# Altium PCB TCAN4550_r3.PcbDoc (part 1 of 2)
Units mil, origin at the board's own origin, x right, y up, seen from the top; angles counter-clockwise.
Board outline 2000 x 1400 mil, 2 copper layers (Top Layer, Bottom Layer), stack 62 mil thick; 75 components, 46 nets, 194 pads, 17 vias.
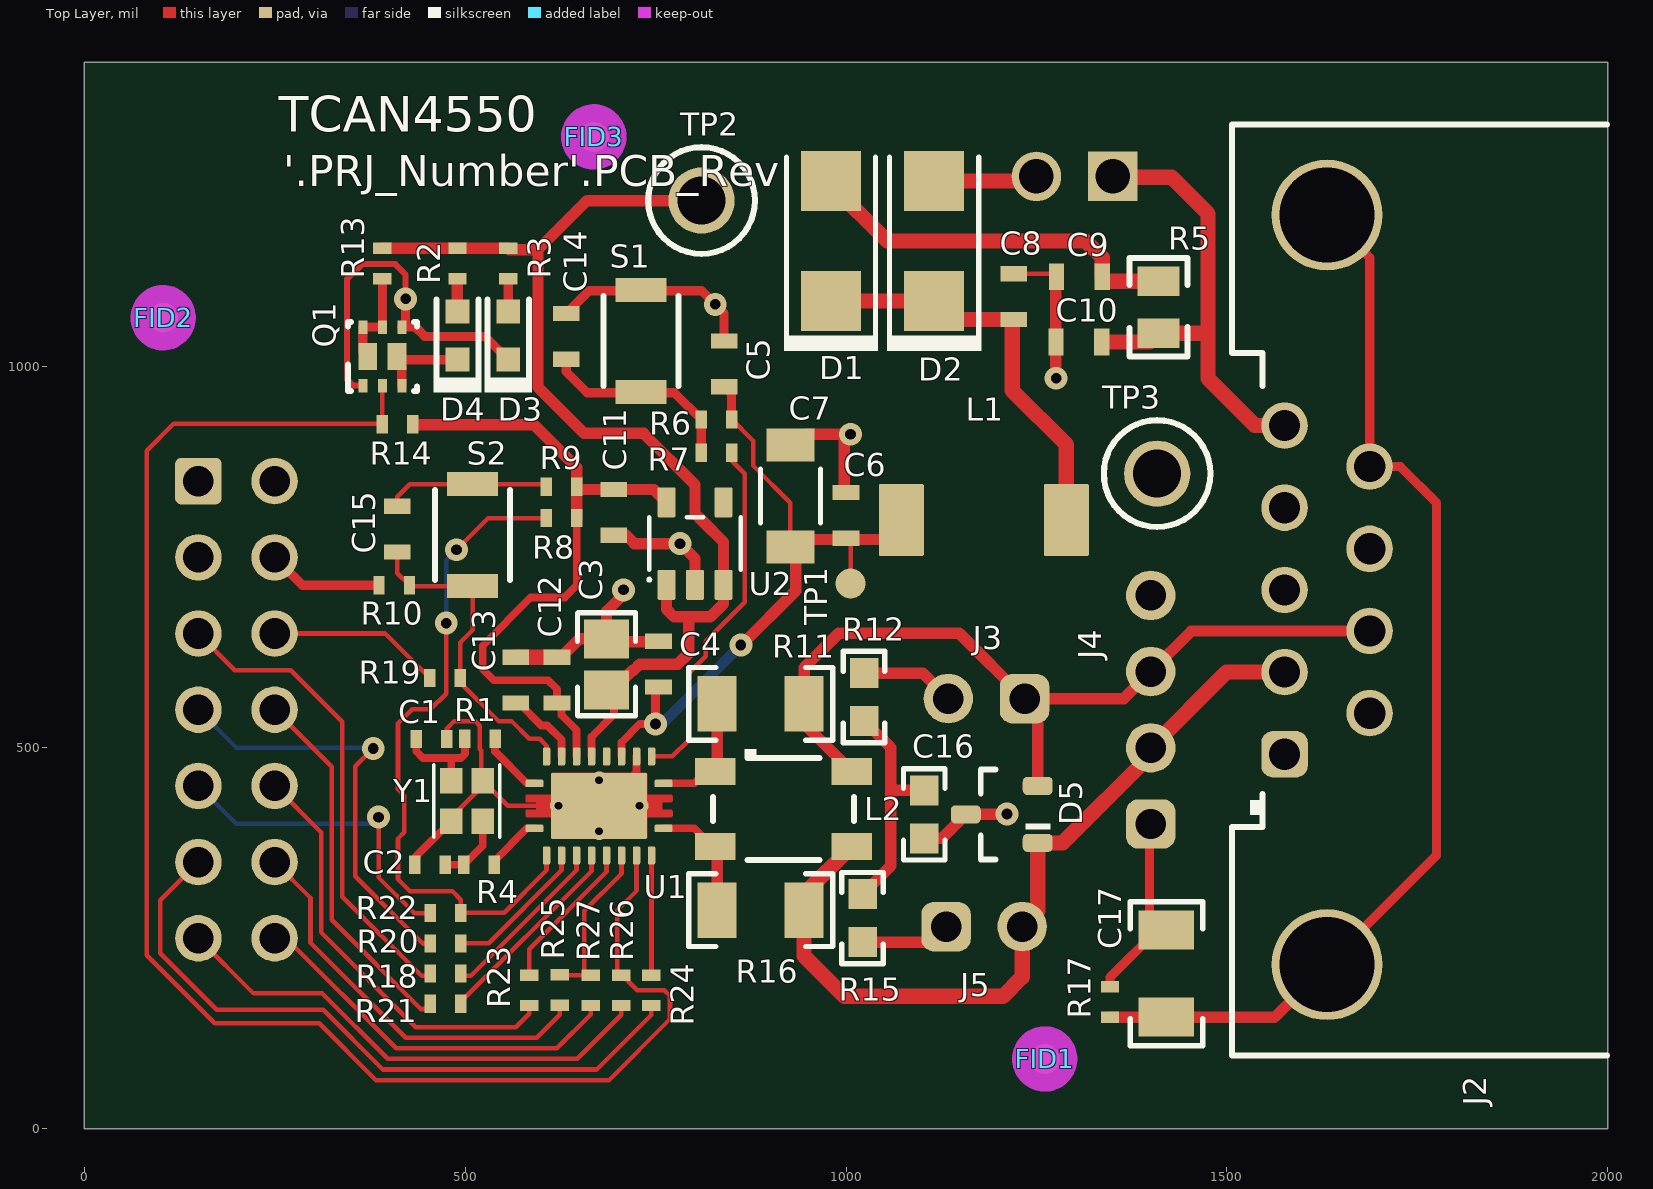
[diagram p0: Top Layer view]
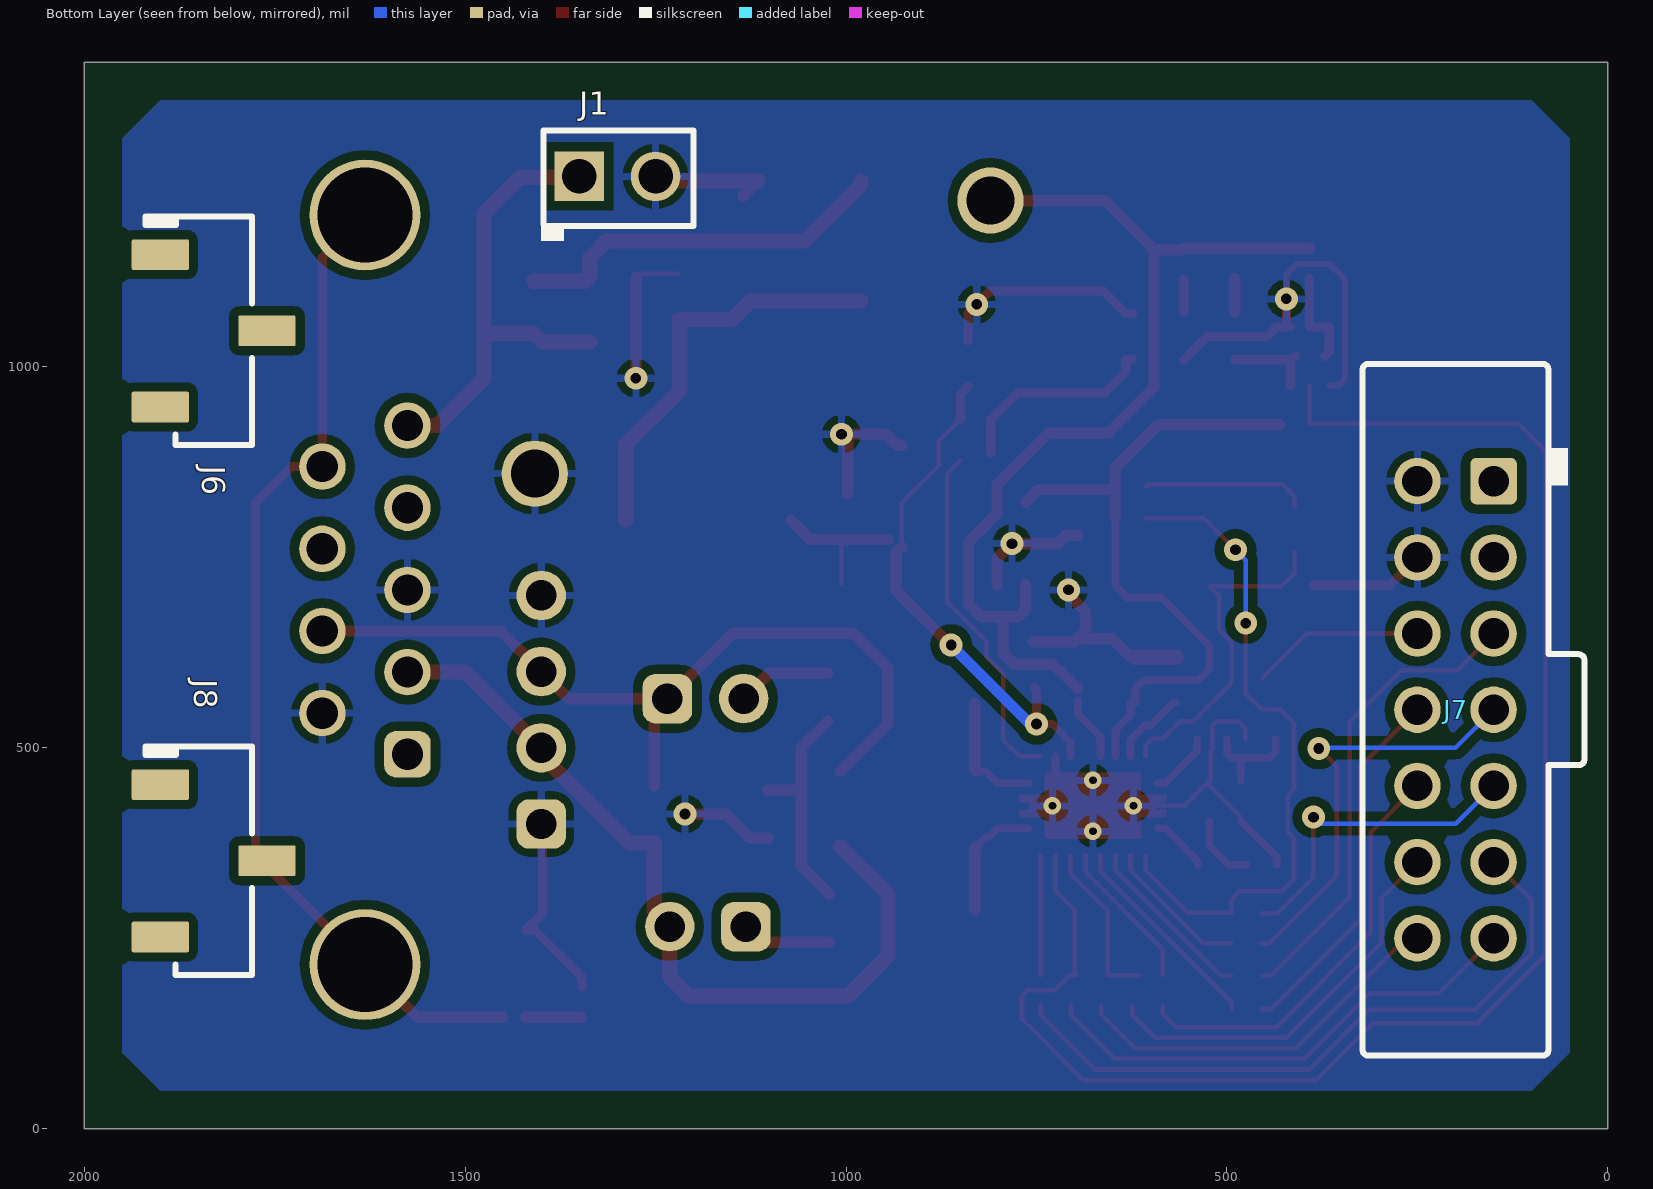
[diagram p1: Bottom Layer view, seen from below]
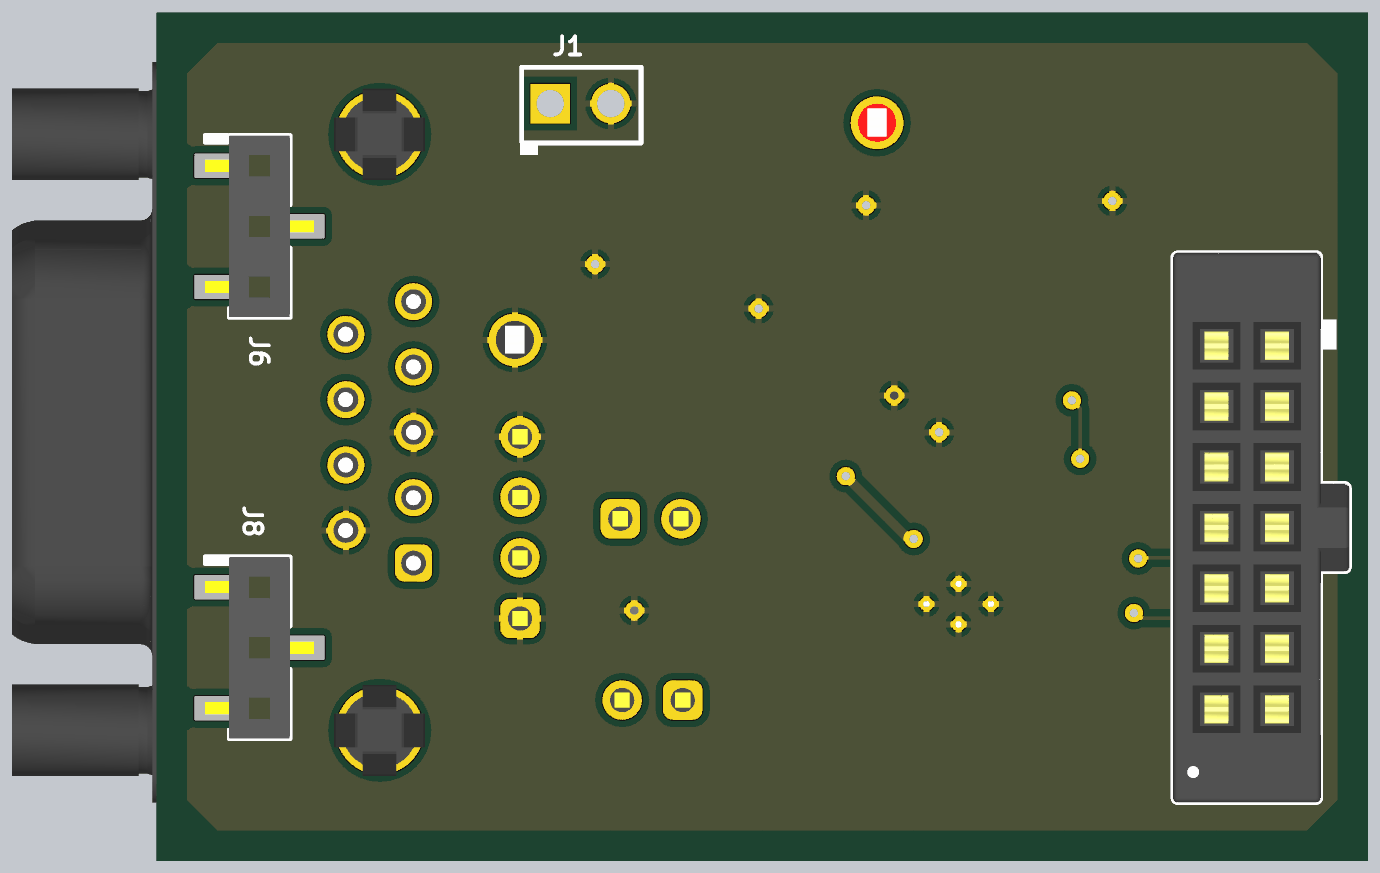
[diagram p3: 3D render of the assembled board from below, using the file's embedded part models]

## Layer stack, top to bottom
Top Solder: solder mask 0.4, Solder Resist, Dk 3.5
Top Layer: signal copper 1.4
Dielectric1: core 59.2, FR-4, Dk 4.8
Bottom Layer: signal copper 1.4
Bottom Solder: solder mask 0.4, Solder Resist, Dk 3.5

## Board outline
0,0 0,1400 2000,1400 2000,0

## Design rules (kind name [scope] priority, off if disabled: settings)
AcuteAngle [All] p1: minimum=4.50000000000000E+0001 checktracksonly=FALSE
AssemblyTestPointUsage [All] p1: valid=2
BoardOutlineClearance BoardOutlineClearance_MountingHoles [OnCopper and InComponentClass('Mounting Holes')] p1: gap=39.37 ignorepadtopadclearanceinfootprint=FALSE
BoardOutlineClearance BoardOutlineClearance_Poly [OnCopper and IsPoly] p2: gap=25 ignorepadtopadclearanceinfootprint=FALSE
BoardOutlineClearance [OnCopper and Not InComponentClass('Logo') and not InComponentClass('FiducialMark') and not InRegion(1000,500,4000,800) and not InPoly] p3: gap=60 ignorepadtopadclearanceinfootprint=FALSE
Clearance Clearance_Keepouts [((IsTrack Or IsArc) And Not InPoly) And IsFree and IsKeepOut vs ((IsTrack Or IsArc) And Not InPoly) And IsFree and IsKeepOut] p1: gap=0 ignorepadtopadclearanceinfootprint=FALSE
Clearance Clearance_Poly [InPolygon] p2: gap=12 ignorepadtopadclearanceinfootprint=TRUE
Clearance Clearance_FiducialMark [IsKeepOut and InComponentClass('FiducialMark') vs IsPad and InComponentClass('FiducialMark')] p3: gap=0 ignorepadtopadclearanceinfootprint=FALSE
Clearance [All] p4: gap=7.87 ignorepadtopadclearanceinfootprint=TRUE
ComponentClearance ComponentClearance_MountingHoles_FiducialMarks [InComponentClass('Mounting Holes') vs InComponentClass('FiducialMark')] p1: gap=50 collisioncheckmode=3 verticalgap=10 showdistances=FALSE
ComponentClearance ComponentClearance_Shunt [InComponentClass('Header') vs InComponentClass('Shunt')] p2: gap=0 collisioncheckmode=3 verticalgap=0 showdistances=FALSE
ComponentClearance ComponentClearance_Logo [InComponentClass('Logo')] p3: gap=10 collisioncheckmode=3 verticalgap=10 showdistances=FALSE
ComponentClearance ComponentClearance_ScrewToNut [(HasFootprint('NY PMS 440 0025 PH')) vs (HasFootprint('Keystone_1902C'))] p4: gap=5 collisioncheckmode=3 verticalgap=10 showdistances=FALSE
ComponentClearance ComponentClearance_MountingHoles [InComponentClass('Mounting Holes')] p5: gap=250 collisioncheckmode=3 verticalgap=100000 showdistances=FALSE
ComponentClearance ComponentClearance_SmallPassives [HasFootprint('0201*') or HasFootprint('0402*') or HasFootprint('0508') or HasFootprint('0603*') or HasFootprint('0612') or HasFootprint('0805*') or HasFootprint('0815*') or HasFootprint('0830*') or HasFootprint('1206*') or HasFootprint('1210*') or HasFootprint('1808*') or HasFootprint('1812*') or HasFootprint('1825*') or HasFootprint('2010*') or HasFootprint('2220*') or HasFootprint('2225*') or HasFootprint('2512*') or HasFootprint('2728*') or HasFootprint('3518*') vs HasFootprint('0201*') or HasFootprint('0402*') or HasFootprint('0508') or HasFootprint('0603*') or HasFootprint('0612') or HasFootprint('0805*') or HasFootprint('0815*') or HasFootprint('0830*') or HasFootprint('1206*') or HasFootprint('1210*') or HasFootprint('1808*') or HasFootprint('1812*') or HasFootprint('1825*') or HasFootprint('2010*') or HasFootprint('2220*') or HasFootprint('2225*') or HasFootprint('2512*') or HasFootprint('2728*') or HasFootprint('3518*')] p6: gap=14.96 collisioncheckmode=3 verticalgap=10 showdistances=FALSE
ComponentClearance ComponentClearance_THtoSMT [IsThruComponent vs IsSMTComponent] p7: gap=40 collisioncheckmode=3 verticalgap=30 showdistances=FALSE
ComponentClearance ComponentClearance_THtoTH [IsThruComponent vs IsThruComponent] p8: gap=30 collisioncheckmode=3 verticalgap=30 showdistances=FALSE
ComponentClearance [All] p9: gap=30 collisioncheckmode=3 verticalgap=10 showdistances=FALSE
DiffPairsRouting [All] p1: maxlimit=100 minlimit=10 mostfreqgap=10 toplayer_minwidth=15 toplayer_maxwidth=15 toplayer_prefwidth=15 bottomlayer_minwidth=15 bottomlayer_maxwidth=15 bottomlayer_prefwidth=15 maxuncoupledlength=1000
FabricationTestPointUsage TestPointUsage [All] p1: valid=2 allowmultiple=FALSE
FabricationTestpoint Testpoint [All] p1: side=3 testpointundercomponent=TRUE minsize=40 maxsize=100 preferedsize=60 minholesize=0 maxholesize=40 preferedholesize=32 testpointgrid=1 allowsidetop=TRUE allowsidebottom=TRUE usegrid=TRUE gridtolerance=0.01
FanoutControl Fanout_LCC [IsLCC] p1: bgadir=Out bgaviamode=Centered fanoutstyle=Auto fanoutdirection=Alternating viagrid=1 // Fanout_LCC (Default Rule)
FanoutControl Fanout_BGA [IsBGA] p2: bgadir=Out bgaviamode=Centered fanoutstyle=Auto fanoutdirection=Alternating viagrid=1 // Fanout_BGA (Default Rule)
FanoutControl Fanout_Default [All] p4: bgadir=Out bgaviamode=Centered fanoutstyle=Auto fanoutdirection=Alternating viagrid=1 // Fanout_Default (Default Rule)
FanoutControl Fanout_Small [(CompPinCount < 5)] p5: bgadir=Out bgaviamode=Centered fanoutstyle=Auto fanoutdirection=OutThenIn viagrid=1 // Fanout_Small (Default Rule)
HoleSize [All] p1: absolutevalues=TRUE maxlimit=251 minlimit=7.87 maxpercent=80.000 minpercent=20.000
MinimumAnnularRing MinimumAnnularRing_ThermalPadVias [IsVia and InAnyComponent] p1: minimumring=5.91
MinimumAnnularRing [All] p2: minimumring=7.87
MinimumSolderMaskSliver MinimumSolderMaskSliver_Logo [InComponentClass('Logo') vs InComponentClass('Logo')] p1: minsoldermaskwidth=0.7
MinimumSolderMaskSliver [All] p2: minsoldermaskwidth=3.94
PlaneConnect [All] p1: planeconnectstyle=Relief reliefexpansion=10 reliefentries=4 reliefconductorwidth=10 reliefairgap=10
PolygonConnect [All] p1: connectstyle=Relief reliefconductorwidth=10 reliefentries=4 polygonreliefangle="90 Angle" airgapwidth=10
RoutingVias ThermalPadVias [IsVia and InAnyComponent] p1: holewidth=7.87 width=19.68 viastyle="Through Hole" minholewidth=7.87 minwidth=19.68 maxholewidth=12.99 maxwidth=23.62
RoutingVias [All] p2: holewidth=16 width=34 viastyle="Through Hole" minholewidth=7.87 minwidth=26 maxholewidth=40 maxwidth=65
SilkToBoardRegionClearance [Not ((IsComment or IsDesignator) And (Hide <> 'False')) and not InRegion(1000,500,4000,800)] p1:
SilkToSilkClearance SilkToSilkClearance_Pb-FreeLogo [(HasFootprint('Pb-Free_Overlay_Medium') OR HasFootprint('Pb-Free_Overlay_Small')) vs (HasFootprint('Pb-Free_Overlay_Medium') OR HasFootprint('Pb-Free_Overlay_Small'))] p1: silktosilkclearance=0
SilkToSilkClearance [All] p2: silktosilkclearance=3.94
SilkToSolderMaskClearance SilkToComponentPadClearance [(IsPad or IsFill or IsRegion) and InAnycomponent] p1: minsilkscreentomaskgap=5 clearancetoexposedcopper=TRUE
SilkToSolderMaskClearance "Silk to Solder Mask Opening" [All] p2: minsilkscreentomaskgap=3.94 clearancetoexposedcopper=FALSE
SolderMaskExpansion [All] p1: expansion=1.97
UnRoutedNet [All] p1: checkbadconnections=TRUE
Width [All] p1: maxlimit=100 minlimit=6 preferedwidth=10 checkconnectedcopper=TRUE
14 further rules are at their usual default settings.

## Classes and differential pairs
component class Header: J3 J4 J5
component class FiducialMark: FID1 FID2 FID3
component class AssemblyNote: ZZ1 ZZ2 ZZ3 ZZ4

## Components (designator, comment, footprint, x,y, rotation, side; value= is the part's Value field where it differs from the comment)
C1 "CC0402DRNPO9BN8R0" 0402S 455.89,511.49 r0 top value=8pF
C2 "CC0402DRNPO9BN8R0" 0402S 454.24,346.43 r180 top value=8pF
C3 "CL21B106KOQNNNE" 0805 685.69,609.54 r90 top value=10uF
C4 "CGA3E2X7R1H104K080AA" 0603S 753.8,609.75 r90 top value=0.1uF
C5 "CGA3E2X7R1H104K080AA" 0603S 840,1004 r90 top value=0.1uF
C6 "UMK107AB7105KA-T" 0603S 1000,805 r90 top value=1uF
C7 "CL31B106KBHNNNE" 1206_180 927,830.43 r90 top value=10uF
C8 "CGA3E2X7R2A102K080AA" 0603S 1220,1092.16 r90 top value=1000pF
C9 "CGA3E2X7R2A102K080AA" 0603S 1306.31,1118.1 r180 top value=1000pF
C10 "CGA3E2X7R2A102K080AA" 0603S 1305.54,1032.57 r180 top value=1000pF
C11 "CGA3E2X7R1H104K080AA" 0603S 695.33,809 r270 top value=0.1uF
C12 "CGA3E2X7R1H104K080AA" 0603S 620.73,588.9 r90 top value=0.1uF
C13 "C0603C334K4RACTU" 0603S 566.37,588.9 r90 top value=0.33uF
C14 "06035A101JAT2A" 0603S 632.78,1040 r90 top value=100pF
C15 "06035A101JAT2A" 0603S 411.13,787.12 r90 top value=100pF
C16 "06031C472KAT2A" 0603 1102.8,412.74 r90 top value=4700pF
C17 "12061C103JAT2A" 1206 1420.58,203.51 r90 top value=0.01uF
D1 "MBRA140T3G" SMA 980.32,1165.07 r90 top value=40V
D2 "3SMAJ5936B-TP" SMA 1115.6,1165.07 r90 top value=30V
D3 "150060GS75000" WL-SMCW_GREEN 556.7,1040.86 r90 top value=Green
D4 "150060BS75000" WL-SMCW_Blue 490.1,1040.86 r90 top value=Blue
D5 "PESD1CAN,215" SOT-23 1204.42,412.6 r180 top value=24V
FID1 "Fiducial" Fiducial10-20 1260.92,91.64 r0 top
FID2 "Fiducial" Fiducial10-20 103.75,1064.48 r0 top
FID3 "Fiducial" Fiducial10-20 669,1301.88 r0 top
J1 "SSW-101-23-F-D" Samtec_SSW-101-23-x-D 1300,1250 r90 bottom
J2 "5747840-5" TE_5747840-5 2006.81,707.26 r90 top
J3 "TSW-102-07-G-S" TSW-102-07-G-S 1184.31,564.55 r180 top
J4 "TSW-104-07-G-S" TSW-104-07-G-S 1400,550 r90 top
J5 "TSW-102-07-G-S" TSW-102-07-G-S 1181.27,265.3 r0 top
J6 "SSM-103-S-SV" Samtec_SSM-103-x-SV 1829.98,1047.31 r270 bottom
J7 "SFH11-PBPC-D07-ST-BK" Sullins_SFH11-xxxC-D07-ST-BK 200,550 r270 bottom
J8 "SSM-103-S-SV" Samtec_SSM-103-x-SV 1829.98,351.72 r270 bottom
L1 "B82462A4472M000" B82462A4 1180.91,799 r0 top value=4.7uH
L2 "ACT45B-101-2P-TL003" ACT45B 917.96,419.83 r0 top value=100uH
Q1 "CSD85301Q2" DQK0006B 391.4,1013.87 r90 top value=20V
R1 "RC0402JR-070RL" 0402S 519.38,511.86 r180 top value=0
R2 "RC0402FR-071KL" 0402S 490,1135.47 r90 top value=1.00k
R3 "RC0402FR-0710KL" 0402S 556.7,1135.47 r90 top value=10.0k
R4 "RC0402JR-070RL" 0402S 518.14,346.43 r180 top value=0
R5 "5106" 5106 1410.15,1078.75 r270 top value=0
R6 "ERJ-2RKF3301X" 0402S 829.89,931 r0 top value=3.30k
R7 "CRCW040233K2FKED" 0402S 830,887.08 r0 top value=33.2k
R8 "RC0402FR-0710KL" 0402S 626.63,801.58 r0 top value=10.0k
R9 "RC0402FR-071KL" 0402S 626.63,842.48 r0 top value=1.00k
R10 "RC1005F104CS" 0402S 407.05,713.42 r0 top value=100k
R11 "ERJ-8GEY0R00V" 1206 887.96,557.75 r0 top value=0
R12 "RC0603FR-0760R4L" 0603 1023.79,566.61 r90 top value=60.4
R13 "RC0402FR-0710KL" 0402S 391.44,1135.47 r90 top value=10.0k
R14 "RC0402FR-0710KL" 0402S 411.13,924.5 r0 top value=10.0k
R15 "RC0603FR-0760R4L" 0603 1021.72,276.36 r90 top value=60.4
R16 "ERJ-8GEY0R00V" 1206 887.96,286.88 r0 top value=0
R17 "ERJ-2RKF1004X" 0402S 1346.5,166.15 r270 top value=1.00Meg
R18 "RC0402JR-070RL" 0402S 474.24,203.72 r180 top value=0
R19 "RC0402JR-070RL" 0402S 473.57,591.55 r0 top value=0
R20 "RC0402JR-070RL" 0402S 474.34,243.12 r180 top value=0
R21 "RC0402JR-070RL" 0402S 474.24,164.1 r0 top value=0
R22 "RC0402JR-070RL" 0402S 474.34,283.14 r180 top value=0
R23 "RC0402JR-070RL" 0402S 584.26,181.74 r90 top value=0
R24 "RC0402JR-070RL" 0402S 744.53,181.74 r270 top value=0
R25 "RC0402JR-070RL" 0402S 624.46,181.91 r90 top value=0
R26 "RC0402JR-070RL" 0402S 705,181.74 r270 top value=0
R27 "RC0402JR-070RL" 0402S 665,181.74 r90 top value=0
S1 "B3U-1000P" SW_B3U-1000P 730.74,1034 r270 top
S2 "B3U-1000P" SW_B3U-1000P 510,779 r270 top
TP1 "TP_SM_1MM" TP_SM_1MM 1006,715.63 r0 top
TP2 "5010" Keystone5010 810.46,1218.28 r180 top
TP3 "5011" Keystone5011 1408.36,859.88 r180 top
U1 "TCAN4550RGYRQ1" RGY0020C 675.85,423.77 r90 top
U2 "TPS73433TDDCRQ1" DDC0005A_N 801.82,768 r90 top
Y1 "NX2016SA-40M-STD-CZS-3" XTAL_NX2016SA 502.33,430.01 r270 top
ZZ1 "This Assembly Note is for PCB labels only" AssemblyNoteLabel 35,2288 r0 top
ZZ2 "These assemblies are ESD sensitive, ESD precautions shall be observed." AssemblyNote 35,2179.11 r0 top
ZZ3 "These assemblies must be clean and free from flux and all contaminants. Use of no clean flux is not acceptable." AssemblyNote 35,2090.56 r0 top
ZZ4 "These assemblies must comply with workmanship standards IPC-A-610 Class 2, unless otherwise specified." AssemblyNote 35,2002 r0 top

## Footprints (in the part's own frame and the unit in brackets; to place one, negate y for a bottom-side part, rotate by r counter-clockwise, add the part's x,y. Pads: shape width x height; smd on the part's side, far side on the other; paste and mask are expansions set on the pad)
0402S [mil] "Based on C0402S footprint from PADS legacy"
  rect 15x24 smd: 1(-20,0) 2(20,0)
  body extent -22,-12 22,12, height 24
0603 [mm] "0603 from SM-752 data"
  rect 1x0.95 smd: 1(-0.8,0) 2(0.8,0)
  silkscreen extent -1.52,-0.69 1.52,0.69, body extent -0.87,-0.47 0.87,0.47, height 1
0603S [mil]
  rect 20x35 smd: 1(-30,0) 2(30,0)
  body extent -34,-19 34,19, height 39
0805 [mm] "0805 from SM-752 data"
  rect 1.3x1.5 smd: 1(-0.85,0) 2(0.85,0)
  silkscreen extent -1.72,-0.97 1.72,0.97, body extent -1.1,-0.72 1.1,0.72, height 1.45
1206 [mm] "1206 from SM-752 data"
  rect 1.3x1.85 smd: 1(-1.45,0) 2(1.45,0)
  silkscreen extent -2.4,-1.21 2.4,1.21, body extent -1.7,-0.9 1.7,0.9, height 1.35
1206_180 [mm] "1206_180"
  rect 1.1x1.6 smd: 1(-1.7,0) 2(1.7,0)
  silkscreen extent -0.9,-1 0.9,1, body extent -1.75,-0.95 1.75,0.95, height 1.8
5106 [mm] "Keystone"
  rect 0.99x1.4 smd: 1(-0.85,0) 2(0.88,0)
  silkscreen extent -1.63,-0.97 1.65,0.97, body extent -1.06,-0.69 1.06,0.69, height 0.84
ACT45B [mm] "SMD, 4-Leads, Body 4.7 x 3.7 mm"
  rect 1.35x0.9 smd: 1(-2.275,1.25) 2(-2.275,-1.25) 3(2.275,-1.25) 4(2.275,1.25)
  silkscreen extent -2.35,-1.7 2.35,2, body extent -2.35,-1.7 2.35,1.7, height 3
AssemblyNote [mil] "Assembly Note"
AssemblyNoteLabel [mil] "Assembly Note for PCB Labels"
B82462A4 [mm] "SMD, 2-Leads, Body 6x6mm"
  rrect7% 1.5x2.4 smd: 1(-2.75,0) 2(2.75,0)
  body extent -3.1,-3.05 3.1,2.94, height 3
DDC0005A_N [mm]
  rrect17% 1x0.6 smd: 1(-1.375,0.95) 2(-1.375,0) 3(-1.375,-0.95) 4(1.375,-0.95) 5(1.375,0.95)
  silkscreen extent -1.25,-1.52 0.88,1.57, body extent -1.41,-1.45 1.41,1.45, height 1.1
DQK0006B [mm] "TI"
  rect 0.45x0.3 smd: 1(-0.975,0.65) 2(-0.975,0) 3(-0.975,-0.65) 4(0.975,-0.65) 5(0.975,0) 6(0.975,0.65)
  rect 0.9x0.625 smd paste-0.025: 7(0,0.488) 8(0,-0.488)
  silkscreen extent -1.15,-1.15 1.15,1.15, body extent -1.05,-1.05 1.05,1.05, height 0.8
Fiducial10-20 [mm]
  round 1 smd mask+0.5: 1(0,0)
  Top Layer keep-out circle w1.178: c0,0 r0.5
Keystone5010 [mil] "Keystone Multipurpose loops"
  round 87 hole 63: 1(0,0)
  silkscreen extent -70,-70 70,70, body extent -63,-63 63,62, height 319
Keystone5011 [mil] "Keystone Multipurpose loops"
  round 87 hole 63: 1(0,0)
  silkscreen extent -70,-70 70,70, body extent -63,-63 63,62, height 319
RGY0020C [mm] "VQFN-20"
  rrect40% 0.25x0.6 smd: 1(-0.75,2.15) 10(-0.75,-2.15) 11(0.75,-2.15) 20(0.75,2.15)
  rrect40% 0.6x0.25 smd: 2(-1.65,1.75) 3(-1.65,1.25) 4(-1.65,0.75) 5(-1.65,0.25) 6(-1.65,-0.25) 7(-1.65,-0.75) 8(-1.65,-1.25) 9(-1.65,-1.75) 12(1.65,-1.75) 13(1.65,-1.25) 14(1.65,-0.75) 15(1.65,-0.25) 16(1.65,0.25) 17(1.65,0.75) 18(1.65,1.25) 19(1.65,1.75)
  rrect5% 2.2x3.2 smd paste-1.4: 21(0,0)
  Top Layer region: -0.375,-1.6 -1.05,-1.6 -1.069,-1.596 -1.085,-1.585 -1.096,-1.569 -1.1,-1.55 -1.1,-1.55 -1.1,1.55 -1.096,1.569 -1.085,1.585 -1.069,1.596 -1.05,1.6 -1.05,1.6 -0.375,1.6 -0.375,2.4 -0.371,2.419 -0.36,2.435 -0.344,2.446 -0.325,2.45 -0.325,2.45 -0.175,2.45 -0.156,2.446 -0.14,2.435 -0.129,2.419 -0.125,2.4 -0.125,2.4 -0.125,2.1 0.125,2.1 0.125,2.4 0.129,2.419 0.14,2.435 0.156,2.446 0.175,2.45 0.175,2.45 0.325,2.45 0.344,2.446 0.36,2.435 0.371,2.419 0.375,2.4 0.375,2.4 0.375,1.6 1.05,1.6 1.069,1.596 1.085,1.585 1.096,1.569 1.1,1.55 1.1,1.55 1.1,-1.55 1.096,-1.569 1.085,-1.585 1.069,-1.596 1.05,-1.6 1.05,-1.6 0.375,-1.6 0.375,-2.4 0.371,-2.419 0.36,-2.435 0.344,-2.446 0.325,-2.45 0.325,-2.45 0.325,-2.45 0.175,-2.45 0.175,-2.45 0.156,-2.446 0.14,-2.435 0.129,-2.419 0.125,-2.4 0.125,-2.4 0.125,-2.1 -0.125,-2.1 -0.125,-2.4 -0.129,-2.419 -0.14,-2.435 -0.156,-2.446 -0.175,-2.45 -0.175,-2.45 -0.175,-2.45 -0.325,-2.45 -0.325,-2.45 -0.344,-2.446 -0.36,-2.435 -0.371,-2.419 -0.375,-2.4 -0.375,-2.4
  body extent -1.75,-2.25 1.75,2.25, height 1
Samtec_SSM-103-x-SV [mm] "Receptacle, 2.54mm, 3x1, SMT"
  rrect10% 1.02x1.905 smd: 1(-2.54,-1.777) 2(0,1.777) 3(2.54,-1.777)
  silkscreen extent -3.81,-2.27 3.81,1.28, body extent -3.81,-2.29 3.81,2.29, height 7.51
Samtec_SSW-101-23-x-D [mm] "SAMTEC"
  rect 1.65x1.65 hole 1.15: 1(0,1.27)
  round 1.65 hole 1.15: 2(0,-1.27)
  silkscreen extent -2.16,-2.54 1.52,2.54, body extent -1.52,-2.49 1.52,2.46, height 8.59
SMA [mm] "Molded Diode, 2-Leads, Body 4.3x2.6mm, IPC Medium Density, based on OnSemi component dimensions and land pattern"
  rect 2x2 smd: 1(-2,0) 2(2,0)
  silkscreen extent -3.66,-1.57 2.79,1.57, body extent -2.6,-1.3 2.6,1.3, height 2.42
SOT-23 [mm] "SOT23, 3-Leads, Body 2.9x1.3mm, Pitch 0.95mm, Lead Span 2.5mm, IPC Medium Density"
  rrect50% 1x0.6 smd: 1(-1.2,0.95) 2(-1.2,-0.95) 3(1.2,0)
  silkscreen extent -1.63,-1.5 0.7,1.5, body extent -1.16,-1.45 1.21,1.45, height 1
Sullins_SFH11-xxxC-D07-ST-BK [mm] "Receptacle, 2.54mm, 7x2, TH"
  rrect25% 1.55x1.55 hole 1.02: 1(-7.62,1.27)
  round 1.55 hole 1.02: 2(-7.62,-1.27) 3(-5.08,1.27) 4(-5.08,-1.27) 5(-2.54,1.27) 6(-2.54,-1.27) 7(0,1.27) 8(0,-1.27) 9(2.54,1.27) 10(2.54,-1.27) 11(5.08,1.27) 12(5.08,-1.27) 13(7.62,1.27) 14(7.62,-1.27)
  silkscreen extent -11.53,-3.1 11.53,4.3, body extent -11.53,-3.1 11.53,4.3, height 8.71
SW_B3U-1000P [mm] "OMRON"
  rect 0.8x1.7 smd: 1(-1.7,0) 2(1.7,0)
  silkscreen extent -1.5,-1.25 1.5,1.25, body extent -1.5,-1.25 1.5,1.25, height 1.75
TE_5747840-5 [mm] "D-Sub, 2.74mm, 9 Position, R/A, TH"
  rrect50% 1.55x1.55 hole 1.04: 1(-5.48,10.954)
  round 1.55 hole 1.04: 2(-2.74,10.954) 3(0,10.954) 4(2.74,10.954) 5(5.48,10.954) 6(-4.11,8.114) 7(-1.37,8.114) 8(1.37,8.114) 9(4.11,8.114)
  round 3.7 hole 3.17: 10(12.495,9.534) 11(-12.495,9.534)
  silkscreen extent -15.52,0.2 15.52,12.71, body extent -15.52,-5.89 15.52,12.71, height 12.55
TP_SM_1MM [mm] "1mm Test Point, SMT"
  round 1 smd paste-0.5: 1(0,0)
TSW-102-07-G-S [mm] "Samtec 100mil, 1x2, 230 mil above insulator"
  rrect50% 1.65x1.65 hole 1.016: 1(-1.27,0)
  round 1.65 hole 1.016: 2(1.27,0)
  body extent -2.54,-1.27 2.54,1.27, height 8.38
TSW-104-07-G-S [mm] "Samtec 100mil, 1x4, 230 mil above insulator"
  rrect50% 1.65x1.65 hole 1.016: 1(-3.81,0)
  round 1.65 hole 1.016: 2(-1.27,0) 3(1.27,0) 4(3.81,0)
  body extent -5.08,-1.27 5.08,1.27, height 8.38
WL-SMCW_Blue [mm] "SMD, 2-Leads, Body 1.6x0.8mm"
  rect 0.8x0.8 smd: 1(-0.8,0) 2(0.8,0)
  silkscreen extent -1.9,-0.8 1.2,0.8, body extent -0.85,-0.45 0.85,0.45, height 0.8
WL-SMCW_GREEN [mm] "WURTH"
  rect 0.8x0.8 smd: 1(-0.8,0) 2(0.8,0)
  silkscreen extent -1.9,-0.8 1.2,0.8, body extent -0.85,-0.45 0.85,0.45, height 0.8
XTAL_NX2016SA [mm] "2.0 x 1.6 x 0.45mm Crystal"
  rect 0.85x0.75 smd mask+0.076: 1(-0.675,-0.525) 2(0.675,-0.525) 3(0.675,0.525) 4(-0.675,0.525)
  silkscreen extent -1.2,-1.1 1.2,1.1, body extent -1,-0.8 1,0.8, height 0.51

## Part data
C1 C2: library part CMP-0860185-1, "CAP, CERM, 8 pF, 50 V,+/- 6.25%, C0G/NP0, 0402", Cap_Case=0402, Manufacturer=Yageo, TempCo=C0G/NP0, Tolerance_%=6.25%, Value2=50V, ValueDisplayed=8pF
C3: library part CMP-0007995-2, "CAP, CERM, 10 uF, 16 V, +/- 10%, X7R, 0805", Cap_Case=0805, Manufacturer="Samsung Electro-Mechanics", TempCo=X7R, Tolerance_%=10%, Value1=Unknown, Value2=16V, ValueDisplayed=10uF
C4 C5 C11 C12: library part CMP-0007078-4, "CAP, CERM, 0.1 uF, 50 V, +/- 10%, X7R, AEC-Q200 Grade 1, 0603", Cap_Case=0603, Manufacturer=TDK, Supplier Part Number 1=445-5666-1-ND, TempCo=X7R, Tolerance_%=10%, Value1="0.0296 ohm", Value2=50V, ValueDisplayed=0.1uF
C6: library part CMP-0007508-5, "CAP, CERM, 1 uF, 50 V, +/- 10%, X7R, 0603", Cap_Case=0603, Manufacturer="Taiyo Yuden", Supplier Part Number 1=587-3247-1-ND, TempCo=X7R, Tolerance_%=10%, Value1=Unknown, Value2=50V, ValueDisplayed=1uF
C7: library part CMP-0008802-2, "CAP, CERM, 10 uF, 50 V, +/- 10%, X7R, 1206", Cap_Case=1206, Manufacturer=Samsung, Supplier Part Number 1=1276-6767-1-ND, TempCo=X7R, Tolerance_%=10%, Value1=Unknown, Value2=50V, ValueDisplayed=10uF
C8 C9 C10: library part CMP-0007081-4, "CAP, CERM, 1000 pF, 100 V, +/- 10%, X7R, AEC-Q200 Grade 1, 0603", Cap_Case=0603, Manufacturer=TDK, Supplier Part Number 1=445-5806-1-ND, TempCo=X7R, Tolerance_%=10%, Value1="1.97137 ohm", Value2=100V, ValueDisplayed=1000pF
C13: library part CMP-0006924-4, "CAP, CERM, 0.33 uF, 16 V, +/- 10%, X7R, 0603", Cap_Case=0603, Manufacturer=Kemet, Supplier Part Number 1=399-4916-1-ND, TempCo=X7R, Tolerance_%=10%, Value1=Unknown, Value2=16V, ValueDisplayed=0.33uF
C14 C15: library part CMP-0006763-4, "CAP, CERM, 100 pF, 50 V, +/- 5%, C0G/NP0, 0603", Cap_Case=0603, Manufacturer=AVX, Supplier Part Number 1=478-1175-1-ND, TempCo=C0G/NP0, Tolerance_%=5%, Value1="0.119 ohm", Value2=50V, ValueDisplayed=100pF
C16: library part CMP-0006746-5, "CAP, CERM, 4700 pF, 100 V, +/- 10%, X7R, 0603", Cap_Case=0603, Manufacturer=AVX, Supplier Part Number 1=478-1203-1-ND, TempCo=X7R, Tolerance_%=10%, Value1="0.136 ohm", Value2=100V, ValueDisplayed=4700pF
C17: library part CMP-0008484-2, "CAP, CERM, 0.01 uF, 100 V, +/- 5%, X7R, 1206", Cap_Case=1206, Manufacturer=AVX, Supplier Part Number 1=478-3783-1-ND, TempCo=X7R, Tolerance_%=5%, Value1="0.119 ohm", Value2=100V, ValueDisplayed=0.01uF
D1: library part CMP-0028550-2, "Diode, Schottky, 40 V, 1 A, SMA", Manufacturer="ON Semiconductor", Value1=1A, Value2=0.55V
D2: library part CMP-0005515-4, "Diode, Zener, 30 V, 3 W, SMA", Manufacturer="Micro Commercial Components", Power_W=3W
D3: library part CMP-0002905-2, "LED, Green, SMD", Color=Green, Manufacturer="Wurth Elektronik", Value1=W, Value2=3.2V
D4: library part CMP-0002946-3, "LED, Blue, SMD", Color=Blue, Manufacturer="Wurth Elektronik", Power_TotalModule=105mW, Value1=0.105W, Value2=3.2V
D5: library part CMP-0005920-3, "Diode, TVS, Bi, 24 V, 70 Vc, AEC-Q101, SOT-23", Manufacturer="NXP Semiconductor", Value1=200W
FID1 FID2 FID3: library part CMP-0077181-1, "Fiducial mark.  There is nothing to buy or mount.", Manufacturer=N/A
J1: library part CMP-0055671-1, "Receptacle, 2.54mm, 1x2, Gold, TH", Color=Black, Current_A=5.7A, Manufacturer=Samtec, Voltage_V=550V
J2: library part CMP-0054938-4, "D-Sub, 2.74mm, 9 Position, R/A, TH", Color=Black, Manufacturer="TE Connectivity", Supplier Part Number 1=A32093-ND
J3 J5: library part CMP-0075405-2, "Header, 100mil, 2x1, Gold, TH", Color=Black, Current_A=6.3A, Manufacturer=Samtec, Supplier Part Number 1=SAM1029-02-ND, Voltage_V=550V
J4: library part CMP-0075409-2, "Header, 100mil, 4x1, Gold, TH", Color=Black, Current_A=6.3A, Manufacturer=Samtec, Supplier Part Number 1=SAM1029-04-ND, Voltage_V=550V
J6 J8: library part CMP-0078183-1, "Receptacle, 2.54mm, 3x1, Gold with Tin tail, SMT", Color=Black, Current_A=5.2A, Manufacturer=Samtec, Supplier Part Number 1=SAM1152-03-ND, Voltage_V=405V
J7: library part CMP-0054668-1, "Receptacle, 2.54mm, 7x2, Gold, Black, TH", Color=Black, Current_A=3A, Manufacturer="Sullins Connector Solutions", Supplier Part Number 1=S9195-ND, Voltage_V=1kV
L1: library part CMP-0001617-1, "Inductor, Wirewound, Ferrite, 4.7 µH, 1.65 A, 0.08 ohm, AEC-Q200 Grade 0, SMD", Manufacturer=TDK, Supplier Part Number 1=495-2665-1-ND, Value1="0.08 ohm", Value2=1.65A, ValueDisplayed=4.7µH
L2: library part CMP-0062430-2, "Inductor, Ferrite, 100 uH, 0.15 A, 2 ohm, SMD", Manufacturer=TDK, Supplier Part Number 1=445-3959-1-ND, Value1="2 ohm", Value2=0.15A, ValueDisplayed=100uH
Q1: library part CMP-0000208-1, "MOSFET, 2-CH, N-CH, 20 V, 6.7 A, DQK0006B (WSON-6)", Alternate Manufacturer=None, Manufacturer="Texas Instruments", Supplier Part Number 1=296-40010-1-ND, Value1=0.02, Value2="4.2 nC"
R1 R4 R18 R19 R20 R21 R22 R23 R24 R25 R26 R27: library part CMP-0027004-2, "RES, 0, 5%, 0.063 W, 0402", Manufacturer="Yageo America", Power_W=63mW, Supplier Part Number 1=311-0.0JRCT-ND, TempCo="200 ppm/C", Tolerance_%=5%, Value2=0.063W, Value_Code=0000, ValueDisplayed=0
R2 R9: library part CMP-0026725-1, "RES, 1.00 k, 1%, 0.0625 W, 0402", Manufacturer="Yageo America", Power_W=62.5mW, Supplier Part Number 1=311-1.00KLRCT-ND, TempCo="100 ppm/C", Tolerance_%=1%, Value2=0.0625W, Value_Code=1k00, ValueDisplayed=1.00k
R3 R8 R13 R14: library part CMP-0078669-1, "RES, 10.0 k, 1%, 0.063 W, 0402", Manufacturer="Yageo America", Power_W=63mW, Supplier Part Number 1=311-10.0KLRCT-ND, TempCo="100 ppm/C", Tolerance_%=1%, Value2=0.063W, Value_Code=10k0, ValueDisplayed=10.0k
R5: library part CMP-0020833-2, "RES, 0, 1%, 0.5 W, 0805", Manufacturer=Keystone, Power_W=500mW, Supplier Part Number 1=36-5106CT-ND, TempCo=ppm/C, Tolerance_%=1%, Value2=0.5W, Value_Code=0
R6: library part CMP-0026695-1, "RES, 3.30 k, 1%, 0.1 W, AEC-Q200 Grade 0, 0402", Manufacturer=Panasonic, Power_W=100mW, Supplier Part Number 1=P3.30KLCT-ND, TempCo="100 ppm/C", Tolerance_%=1%, Value2=0.1W, Value_Code=3k30, ValueDisplayed=3.30k
R7: library part CMP-0026298-2, "RES, 33.2 k, 1%, 0.063 W, AEC-Q200 Grade 0, 0402", Manufacturer=Vishay-Dale, Power_W=63mW, Supplier Part Number 1=541-33.2KLCT-ND, TempCo="100 ppm/C", Tolerance_%=1%, Value2=0.063W, Value_Code=33k2, ValueDisplayed=33.2k
R10: library part CMP-0026745-1, "RES, 100 k, 1%, 0.063 W, 0402", Manufacturer="Samsung Electro-Mechanics", Power_W=63mW, Supplier Part Number 1=1276-3432-1-ND, TempCo="100 ppm/C", Tolerance_%=1%, Value2=0.063W, Value_Code=100k
R11 R16: library part CMP-0018748-3, "RES, 0, 5%, 0.25 W, AEC-Q200 Grade 0, 1206", Manufacturer=Panasonic, Power_W=250mW, Supplier Part Number 1=P0.0ECT-ND, TempCo="600 ppm/C", Tolerance_%=5%, Value2=0.25W, Value_Code=0000, ValueDisplayed=0
R12 R15: library part CMP-0023213-5, "RES, 60.4, 1%, 0.1 W, 0603", Manufacturer=Yageo, Power_W=100mW, Supplier Part Number 1=311-60.4HRCT-ND, TempCo="100 ppm/C", Tolerance_%=1%, Value2=0.1W, Value_Code=60R4, ValueDisplayed=60.4
R17: library part CMP-0026660-1, "RES, 1.00 M, 1%, 0.1 W, 0402", Manufacturer=Panasonic, Power_W=100mW, Supplier Part Number 1=P1.00MLCT-ND, TempCo="100 ppm/C", Tolerance_%=1%, Value2=0.1W, Value_Code=1M00, ValueDisplayed=1.00M
S1 S2: library part CMP-0002150-2, "SWITCH TACTILE SPST-NO 0.05A 12V", CurrentRating_mA=50A, Manufacturer="Omron Electronic Components", Supplier Part Number 1=SW1020CT-ND
TP1: library part CMP-0003825-1, "1mm Test Point, SMT", Manufacturer=Any
TP2: library part CMP-0055147-1, "Test Point, Multipurpose, Red, TH", Color=Red, Manufacturer=Keystone, Supplier Part Number 1=36-5010-ND
TP3: library part CMP-0055148-1, "Test Point, Multipurpose, Black, TH", Color=Black, Manufacturer=Keystone, Supplier Part Number 1=36-5011-ND
U1: library part CMP-0065224-7, "CAN-FD Controller with Integrated Transceiver, RGY0020A (VQFN-20)", Alternate Manufacturer="Texas Instruments", Alternate PartNumber=TCAN4550RGYQ1, Operating Temperature Range="-40 to 125 C", Rating=Automotive
U2: library part CMP-0035843-1, "Single Output High PSRR LDO, 250 mA, Fixed 3.3 V Output, 2.7 to 6.5 V Input, with Low IQ, 5-pin SOT (DDC), -40 to 105 degC, Green (RoHS & no Sb/Br)", Manufacturer="Texas Instruments", Rating=Automotive
Y1: library part CMP-0085289-1, "Crystal, 40 MHz, 10 ppm, 8 pF, AEC-Q200 Grade 0, SMD", Frequency_Fixed=40MHz, Frequency Stability="25 ppm", Frequency Tolerance="10 ppm", Load Capacitance="8 pF", Manufacturer=NDK
ZZ1: library part CMP-0003616-3
ZZ2: library part CMP-0077236-1
ZZ3: library part CMP-0077237-1
ZZ4: library part CMP-0077238-1

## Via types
v1: diameter 30, hole 14, Top Layer to Bottom Layer, 13 vias
v2: diameter 23, hole 10, Top Layer to Bottom Layer, 4 vias

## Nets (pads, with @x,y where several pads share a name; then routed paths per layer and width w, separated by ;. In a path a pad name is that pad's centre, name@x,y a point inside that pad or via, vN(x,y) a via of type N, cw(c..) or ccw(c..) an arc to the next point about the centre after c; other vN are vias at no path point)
3V3: C11.1 C12.1 R8.2 R9.2 R14.2 U1.17 U2.5 | length 911.8
  Top Layer w10: C12.1@620.73,558.9 620.73,577.04 608.87,588.9 537.46,588.9 523,603.36 523,634 586.33,697.33 630.7,697.33 646.63,713.26 R8.2@646.63,801.58 ; C12.1@626.63,558.9 626.63,542.55 646.32,522.86 U1.17@646.32,488.73
  Top Layer w15: R14.2@431.13,924.02 590.52,924.02 646.63,867.9 R9.2@646.63,842.48 ; R8.2@646.63,801.58 R9.2@646.63,842.48 ; U2.5@764.42,822.13 747.55,839 C11.1@695.33,839 650.11,839 R9.2@646.63,842.48
CAN_GPIO1: J7.7 R20.2 | length 562.8
  Top Layer w6: v1(379.43,499.01) 356,475.59 356,331.38 444.25,243.12 R20.2@454.34,243.12
  Bottom Layer w6: J7.7@150,550 200,500 378.44,500 v1(379.43,499.01)
CAN_GPO2: J7.11 R24.2 | length 890.2
  Top Layer w6: J7.11@150,350 100,300 100,230.32 174.18,156.14 313.86,156.14 392.23,77.77 673.03,77.77 744.53,149.27 R24.2@744.53,161.74
CAN_nINT: J7.13 R26.2 | length 656.8
  Top Layer w6: J7.13@150,250 222.4,177.6 312.4,177.6 398.36,91.64 647.1,91.64 705,149.55 R26.2@705,161.74
CAN_nWRKQ: J7.9 R22.2 | length 431.7
  Top Layer w6: v1(386.47,408.97) 386.47,329.82 433.16,283.14 R22.2@454.34,283.14
  Bottom Layer w6: J7.9@150,450 199.46,400.54 386.47,400.54 v1(386.47,408.97)
CAN_RST: C15.1 R10.2 R19.2 S2.2 U1.19 | length 447.2
  Top Layer w6: C15.1@411.13,757.12 411.13,729.34 R10.2@427.05,713.42 428.4,712.07 S2.2@510,712.07 523,712.07 510,699.07 510,654.67 493.57,638.24 R19.2@493.57,591.55 493.57,585.52 543.98,535.11 561.01,535.11 584.26,511.86 597.85,511.86 606.95,502.76 U1.19@606.95,488.73
CANH: L2.1 R11.1 U1.11 | length 164.2
  Top Layer w10: U1.11@760.49,453.29 801.09,453.29 816.84,469.04 L2.1@828.4,469.04
  Top Layer w15: L2.1@828.4,469.04 830.87,471.52 R11.1@830.87,557.75
CANH_BUS: D5.2 J2.7 J3.1 J4.3 L2.4 R11.2 | length 1113.4
  Top Layer w15: L2.4@1007.53,469.04 945.05,531.53 R11.2@945.05,557.75 945.05,604.93 990.44,650.33 1148.53,650.33 J3.1@1234.31,564.55 J3.1@1242.89,564.55 ; D5.2@1251.66,450 1251.66,555.77 J3.1@1242.89,564.55 ; J2.7@1687.35,653.33 1453.33,653.33 J4.3@1400,600 1364.55,564.55 J3.1@1242.89,564.55
CANL: L2.2 R16.1 U1.10 | length 162.4
  Top Layer w10: U1.10@760.49,394.24 800.8,394.24 811.82,383.22 815.8,383.22 L2.2@828.4,370.62
  Top Layer w15: L2.2@828.4,370.62 830.87,368.14 R16.1@830.87,286.88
